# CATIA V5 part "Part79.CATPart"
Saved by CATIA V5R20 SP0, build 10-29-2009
Part number: FA 053000-2
Revision: ANY
Definition: UNKNOWN
Nomenclature: FA 053000-2
Source: Unknown
Bounding box of the stored display mesh (mm): x -1.5 to 1.5, y 0 to 3.7, z -1.5 to 1.5
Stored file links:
  C:\Users\Utente\Desktop\IO LAVORO\3D X SITO CF\CUMSA\3D files FA\FA 053004-21\Part79.CATPart

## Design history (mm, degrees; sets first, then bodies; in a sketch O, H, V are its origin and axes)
Body1 "Cortar-Extruir1" (main body)
  Solid1: solid without history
